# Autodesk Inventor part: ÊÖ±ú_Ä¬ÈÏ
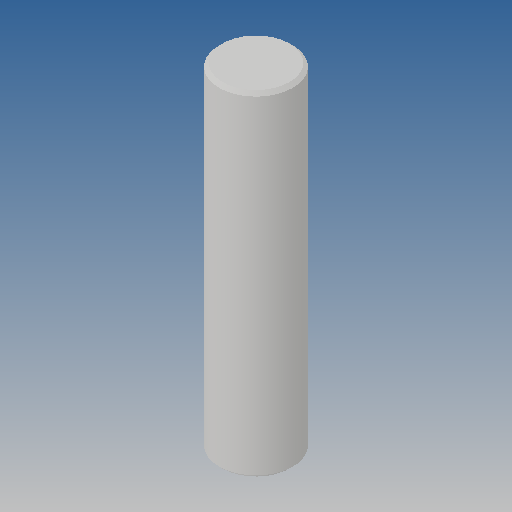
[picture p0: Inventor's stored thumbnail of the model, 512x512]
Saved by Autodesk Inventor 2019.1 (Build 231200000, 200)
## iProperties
Created: 2012-10
Part Number: ÊÖ±ú_Ä¬ÈÏ
Material: Ogólny
Document SubType Name: Modeling
Designer: CADENGINEERING4
Density: 1 g/cm^3
Appearance: Domyślna
Author: CADENGINEERING4
Revision Number: ÈÎºÎ
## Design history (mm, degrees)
feature "NONE"
node "Bryła1"
